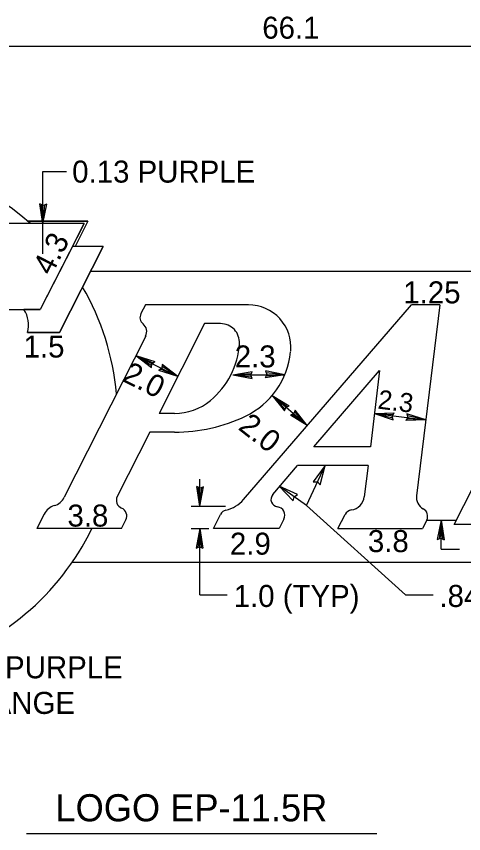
# Model space of a CAD drawing. Extents: x 10268197 to 10269179, y 2141503 to 2142677.
# Drawn here: x 10268616.76 to 10268630.99, y 2141970.23 to 2141996.23 of the extents above; entities that cross this region are included whole.
import ezdxf

# ---------------------------------------------------------------- set-up
doc = ezdxf.new("R2010")
doc.units = 0
for name, color, linetype in [('1', 7, 'Continuous'), ('20', 7, 'Continuous'), ('21', 7, 'Continuous'), ('52', 7, 'Continuous'), ('Default', 7, 'Continuous'), ('NonPlottingEle_dp', 7, 'Continuous')]:
    doc.layers.add(name, color=color, linetype=linetype)

msp = doc.modelspace()

# ---------------------------------------------------------------- linework, layer by layer
at = {"layer": '1'}
for p, q in [((10268618.911, 2141989.641), (10268610.286, 2141989.641)), ((10268619.035, 2141989.717), (10268617.117, 2141989.717)), ((10268618.911, 2141989.641), (10268617.518, 2141986.906)), ((10268619.035, 2141989.717), (10268618.624, 2141988.91)), ((10268618.539, 2141988.91), (10268617.518, 2141986.906)), ((10268618.13, 2141986.175), (10268619.523, 2141988.91)), ((10268619.523, 2141988.91), (10268618.13, 2141986.175)), ((10268619.523, 2141988.91), (10268618.539, 2141988.91)), ((10268619.523, 2141988.91), (10268618.539, 2141988.91)), ((10268619.121, 2141988.121), (10268648.726, 2141988.121)), ((10268620.864, 2141987.054), (10268620.721, 2141986.773)), ((10268624.148, 2141987.054), (10268620.864, 2141987.054)), ((10268623.99, 2141980.859), (10268629.334, 2141987.054)), ((10268630.233, 2141987.054), (10268629.334, 2141987.054)), ((10268630.233, 2141987.054), (10268629.493, 2141980.982)), ((10268616.478, 2141986.906), (10268617.518, 2141986.906)), ((10268617.518, 2141986.906), (10268616.998, 2141986.906)), ((10268622.749, 2141986.456), (10268621.305, 2141983.599)), ((10268623.26, 2141986.456), (10268622.749, 2141986.456)), ((10268618.13, 2141986.175), (10268617.107, 2141986.175)), ((10268617.107, 2141986.175), (10268618.13, 2141986.175)), ((10268620.873, 2141986.058), (10268618.28, 2141980.933)), ((10268626.226, 2141982.536), (10268628.319, 2141984.962)), ((10268628.319, 2141984.962), (10268628.025, 2141982.536)), ((10268621.794, 2141983.6), (10268621.305, 2141983.599)), ((10268621.003, 2141983.001), (10268619.969, 2141980.957)), ((10268621.793, 2141983.002), (10268621.003, 2141983.001)), ((10268628.025, 2141982.536), (10268626.226, 2141982.536)), ((10268624.919, 2141981.021), (10268625.71, 2141981.939)), ((10268627.952, 2141981.939), (10268625.71, 2141981.939)), ((10268627.952, 2141981.939), (10268627.831, 2141980.947)), ((10268630.692, 2141980.066), (10268631.642, 2141981.946)), ((10268617.644, 2141980.4), (10268617.41, 2141979.934)), ((10268620.102, 2141979.934), (10268620.243, 2141980.216)), ((10268623.027, 2141979.935), (10268623.254, 2141980.385)), ((10268625.275, 2141980.24), (10268625.12, 2141979.934)), ((10268626.991, 2141979.934), (10268627.22, 2141980.385)), ((10268629.82, 2141980.206), (10268629.683, 2141979.934)), ((10268620.102, 2141979.934), (10268617.41, 2141979.934)), ((10268625.12, 2141979.934), (10268623.027, 2141979.935)), ((10268626.991, 2141979.934), (10268629.683, 2141979.934)), ((10268631.327, 2141980.066), (10268630.692, 2141980.066)), ((10268618.538, 2141978.866), (10268644.011, 2141978.867))]:
    msp.add_line(p, q, dxfattribs=at)
for centre, radius, start, end in [((10268611.789, 2141983.501), 8.187, 48.5904, 218.8792), ((10268611.789, 2141983.501), 8.187, 5.051, 30.1953), ((10268624.148, 2141985.708), 1.346, 354.6609, 90), ((10268616.266, 2141986.425), 0.877, 343.4611, 33.2756), ((10268616.266, 2141986.425), 0.877, 343.4611, 33.2756), ((10268623.26, 2141985.857), 0.598, 356.6133, 90), ((10268621.319, 2141985.972), 2.542, 309.3947, 356.6133), ((10268622.956, 2141985.808), 2.542, 295.579, 354.2619), ((10268621.793, 2141985.394), 1.795, 270, 309.3947), ((10268621.793, 2141988.236), 5.235, 270, 295.579), ((10268620.209, 2141980.835), 0.269, 153.1708, 247.5682), ((10268625.1, 2141980.865), 0.239, 139.1995, 262.5416), ((10268627.356, 2141981.005), 0.479, 277.9506, 353.082), ((10268629.909, 2141980.932), 0.419, 173.0593, 241.464), ((10268620.004, 2141980.338), 0.269, 333.1431, 67.5682), ((10268625.034, 2141980.361), 0.269, 333.166, 82.5416), ((10268627.46, 2141980.264), 0.269, 97.9506, 153.1923), ((10268629.58, 2141980.328), 0.269, 333.284, 61.464), ((10268611.789, 2141983.501), 8.187, 237.0648, 334.1734)]:
    msp.add_arc(centre, radius, start, end, dxfattribs=at)
for centre, major_axis, start_param, end_param in [((10268620.954, 2141986.653), (0, -0.264), 4.240773, 5.605302), ((10268620.593, 2141986.201), (0, -0.316), 1.099604, 2.46371), ((10268617.815, 2141981.172), (0, -0.527), 0.286787, 1.099486), ((10268623.199, 2141981.552), (0, -1.055), 0.22194, 0.855152), ((10268618.111, 2141980.16), (0, -0.527), 3.428379, 4.240701), ((10268623.487, 2141980.266), (0, -0.264), 3.363532, 4.241567)]:
    msp.add_ellipse(centre, major_axis=major_axis, ratio=0.992614, start_param=start_param, end_param=end_param, dxfattribs=at)
at = {"layer": '20'}
for p, q in [((10268648.726, 2141995.272), (10268601.689, 2141995.272)), ((10268617.601, 2141991.298), (10268618.351, 2141991.299)), ((10268617.601, 2141989.717), (10268617.601, 2141991.298)), ((10268617.601, 2141988.681), (10268617.601, 2141989.641)), ((10268620.562, 2141985.445), (10268621.897, 2141984.77)), ((10268623.644, 2141984.83), (10268625.302, 2141984.83)), ((10268626.018, 2141983.211), (10268624.903, 2141984.173)), ((10268628.153, 2141983.593), (10268629.786, 2141983.395)), ((10268625.99, 2141980.67), (10268626.586, 2141981.947)), ((10268622.598, 2141980.646), (10268622.598, 2141981.505)), ((10268625.99, 2141980.67), (10268625.121, 2141981.287)), ((10268622.316, 2141980.646), (10268623.413, 2141980.646)), ((10268629.147, 2141977.824), (10268625.99, 2141980.67)), ((10268629.82, 2141980.206), (10268630.763, 2141980.207)), ((10268630.276, 2141979.278), (10268630.276, 2141980.206)), ((10268622.316, 2141979.935), (10268622.879, 2141979.935)), ((10268622.598, 2141977.824), (10268622.597, 2141979.934)), ((10268630.276, 2141979.278), (10268630.859, 2141979.277)), ((10268622.598, 2141977.824), (10268623.469, 2141977.824)), ((10268629.147, 2141977.824), (10268630.019, 2141977.824))]:
    msp.add_line(p, q, dxfattribs=at)
at = {"layer": '21'}
for p, q in [((10268617.601, 2141989.641), (10268617.502, 2141990.265)), ((10268617.611, 2141990.215), (10268617.502, 2141990.265)), ((10268617.601, 2141989.641), (10268617.559, 2141990.238)), ((10268617.601, 2141989.641), (10268617.722, 2141990.26)), ((10268617.601, 2141989.641), (10268617.663, 2141990.237)), ((10268617.722, 2141990.26), (10268617.611, 2141990.215)), ((10268620.562, 2141985.445), (10268621.164, 2141985.251)), ((10268620.562, 2141985.445), (10268621.061, 2141985.058)), ((10268620.562, 2141985.445), (10268621.066, 2141985.12)), ((10268620.562, 2141985.445), (10268621.114, 2141985.212)), ((10268621.061, 2141985.058), (10268621.07, 2141985.177)), ((10268621.07, 2141985.177), (10268621.164, 2141985.251)), ((10268621.398, 2141985.157), (10268621.389, 2141985.038)), ((10268621.897, 2141984.77), (10268621.398, 2141985.157)), ((10268621.389, 2141985.038), (10268621.296, 2141984.963)), ((10268621.897, 2141984.77), (10268621.296, 2141984.963)), ((10268621.897, 2141984.77), (10268621.345, 2141985.002)), ((10268621.897, 2141984.77), (10268621.393, 2141985.094)), ((10268623.644, 2141984.83), (10268624.267, 2141984.929)), ((10268623.644, 2141984.83), (10268624.241, 2141984.872)), ((10268624.218, 2141984.82), (10268624.267, 2141984.929)), ((10268625.302, 2141984.83), (10268624.683, 2141984.95)), ((10268624.683, 2141984.95), (10268624.728, 2141984.84)), ((10268625.302, 2141984.83), (10268624.707, 2141984.892)), ((10268623.644, 2141984.83), (10268624.263, 2141984.709)), ((10268623.644, 2141984.83), (10268624.24, 2141984.767)), ((10268624.263, 2141984.709), (10268624.218, 2141984.82)), ((10268624.728, 2141984.84), (10268624.678, 2141984.731)), ((10268625.302, 2141984.83), (10268624.678, 2141984.731)), ((10268625.302, 2141984.83), (10268624.705, 2141984.788)), ((10268624.903, 2141984.173), (10268625.44, 2141983.84)), ((10268624.903, 2141984.173), (10268625.294, 2141983.677)), ((10268624.903, 2141984.173), (10268625.313, 2141983.736)), ((10268624.903, 2141984.173), (10268625.382, 2141983.814)), ((10268625.331, 2141983.79), (10268625.44, 2141983.84)), ((10268625.294, 2141983.677), (10268625.331, 2141983.79)), ((10268625.59, 2141983.593), (10268625.481, 2141983.543)), ((10268626.018, 2141983.211), (10268625.538, 2141983.569)), ((10268625.627, 2141983.707), (10268625.59, 2141983.593)), ((10268626.018, 2141983.211), (10268625.607, 2141983.647)), ((10268626.018, 2141983.211), (10268625.627, 2141983.707)), ((10268628.153, 2141983.593), (10268628.784, 2141983.616)), ((10268628.153, 2141983.593), (10268628.754, 2141983.398)), ((10268628.153, 2141983.593), (10268628.737, 2141983.459)), ((10268628.153, 2141983.593), (10268628.751, 2141983.562)), ((10268628.722, 2141983.514), (10268628.784, 2141983.616)), ((10268629.786, 2141983.395), (10268629.185, 2141983.589)), ((10268629.185, 2141983.589), (10268629.217, 2141983.473)), ((10268626.018, 2141983.211), (10268625.481, 2141983.543)), ((10268628.754, 2141983.398), (10268628.722, 2141983.514)), ((10268629.217, 2141983.473), (10268629.155, 2141983.372)), ((10268629.786, 2141983.395), (10268629.155, 2141983.372)), ((10268629.786, 2141983.395), (10268629.188, 2141983.425)), ((10268629.786, 2141983.395), (10268629.202, 2141983.528)), ((10268622.598, 2141980.646), (10268622.499, 2141981.27)), ((10268622.608, 2141981.221), (10268622.499, 2141981.27)), ((10268622.598, 2141980.646), (10268622.556, 2141981.243)), ((10268622.598, 2141980.646), (10268622.718, 2141981.266)), ((10268622.598, 2141980.646), (10268622.66, 2141981.242)), ((10268622.718, 2141981.266), (10268622.608, 2141981.221)), ((10268630.276, 2141980.206), (10268630.156, 2141979.587)), ((10268630.276, 2141980.206), (10268630.214, 2141979.61)), ((10268630.276, 2141980.206), (10268630.375, 2141979.583)), ((10268630.276, 2141980.206), (10268630.318, 2141979.609)), ((10268622.597, 2141979.934), (10268622.477, 2141979.315)), ((10268622.597, 2141979.934), (10268622.535, 2141979.338)), ((10268622.597, 2141979.934), (10268622.697, 2141979.311)), ((10268622.597, 2141979.934), (10268622.639, 2141979.337)), ((10268630.156, 2141979.587), (10268630.266, 2141979.632)), ((10268630.266, 2141979.632), (10268630.375, 2141979.583)), ((10268622.477, 2141979.315), (10268622.588, 2141979.36)), ((10268622.588, 2141979.36), (10268622.697, 2141979.311))]:
    msp.add_line(p, q, dxfattribs=at)
at = {"layer": '52'}
for p, q in [((10268626.586, 2141981.947), (10268626.209, 2141981.426)), ((10268626.426, 2141981.325), (10268626.586, 2141981.947)), ((10268625.121, 2141981.287), (10268625.565, 2141980.822)), ((10268625.704, 2141981.017), (10268625.121, 2141981.287)), ((10268626.209, 2141981.426), (10268626.339, 2141981.418)), ((10268626.339, 2141981.418), (10268626.426, 2141981.325)), ((10268625.565, 2141980.822), (10268625.597, 2141980.949)), ((10268625.597, 2141980.949), (10268625.704, 2141981.017))]:
    msp.add_line(p, q, dxfattribs=at)
at = {"layer": 'Default'}
msp.add_line((10268617.084, 2141970.232), (10268628.233, 2141970.232), dxfattribs=at)
at = {"layer": 'NonPlottingEle_dp'}
msp.add_lwpolyline([(10268617.117, 2141989.717), (10268619.035, 2141989.717), (10268618.624, 2141988.91), (10268618.539, 2141988.91), (10268618.911, 2141989.641), (10268617.204, 2141989.641)], close=True, dxfattribs=at)

# ---------------------------------------------------------------- texts
at = {"layer": '1'}
msp.add_text('LOGO EP-11.5R', height=0.8624, dxfattribs=at).set_placement((10268618.001, 2141970.624))
at = {"layer": '20'}
for s, p in [('66.1', (10268624.584, 2141995.52)), ('0.13 PURPLE', (10268618.534, 2141990.942)), ('1.25', (10268629.072, 2141987.1)), ('1.5', (10268616.988, 2141985.377)), ('2.3', (10268623.709, 2141985.062)), ('3.8', (10268618.384, 2141980)), ('2.9', (10268623.555, 2141979.106)), ('3.8', (10268627.946, 2141979.188)), ('1.0 (TYP)', (10268623.674, 2141977.443)), ('.84 (TYP)', (10268630.223, 2141977.443)), ('PURPLE', (10268616.398, 2141975.173)), ('ORANGE', (10268614.568, 2141974.041))]:
    msp.add_text(s, height=0.7, dxfattribs=at).set_placement(p)
for s, height, rotation, p in [('4.3', 0.7, 63.001, (10268617.874, 2141987.953)), ('2.0', 0.7, 333.1665, (10268620.087, 2141984.649)), ('2.3', 0.6037, 353.0765, (10268628.239, 2141983.755)), ('2.0', 0.7, 321.8741, (10268623.786, 2141983.113))]:
    msp.add_text(s, height=height, rotation=rotation, dxfattribs=at).set_placement(p)

doc.saveas('drawing.dxf')
